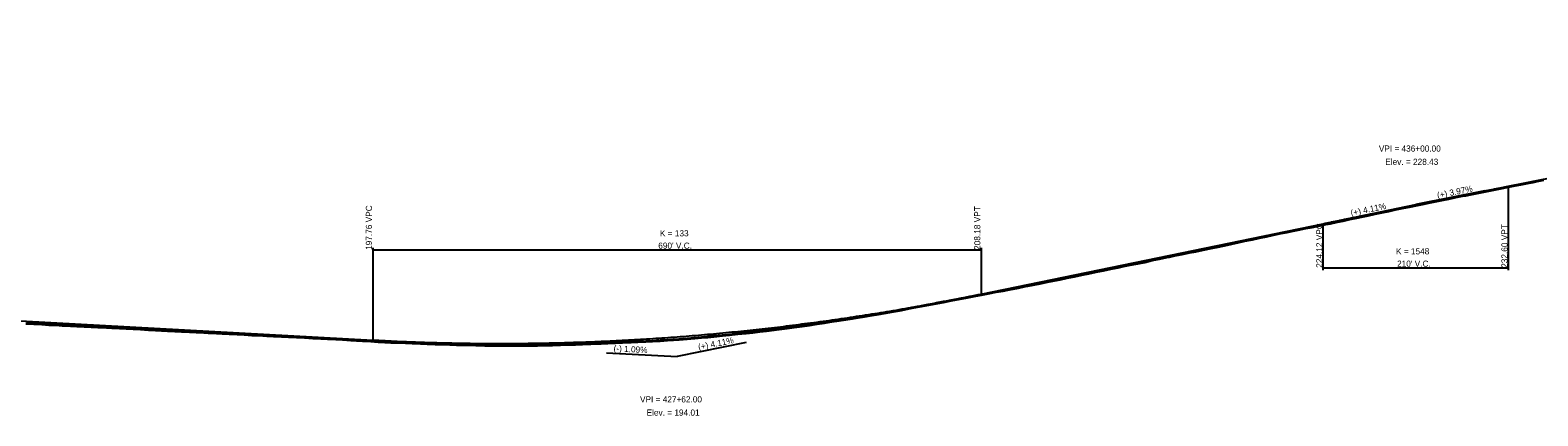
# Model space of a CAD drawing. Extents: x 1876258 to 1926563, y 729739 to 834437.
# Drawn here: x 1920391 to 1922101, y 830907 to 831344 of the extents above; entities that cross this region are included whole.
import ezdxf

# ---------------------------------------------------------------- set-up
doc = ezdxf.new("R2010")
doc.units = 0
for name, color, linetype in [('RD_EX_BldgApp', 7, 'Continuous'), ('RD_EX_H2O_BlueLn', 7, 'Continuous'), ('RD_EX_RailRoad', 7, 'Continuous'), ('RD_HC_Data', 7, 'Continuous'), ('RD_HC_Data_Tic', 7, 'Continuous'), ('RD_HC_TX_Sta50', 7, 'Continuous'), ('RD_PD_ALT5_CL', 7, 'Continuous')]:
    doc.layers.add(name, color=color, linetype=linetype)

msp = doc.modelspace()

# ---------------------------------------------------------------- linework, layer by layer
at = {"layer": 'RD_EX_BldgApp'}
for points in [[(1921856.5, 831122.9), (1921861, 831123.8), (1921866.3, 831124.9), (1921874.3, 831126.6), (1921880.6, 831127.9), (1921888.2, 831129.5), (1921896, 831131.1), (1921901.3, 831132.2), (1921909, 831133.8), (1921916.9, 831135.5), (1921924.6, 831137.1), (1921932.4, 831138.8), (1921940.1, 831140.4), (1921947.5, 831141.9), (1921955.8, 831143.6), (1921964.9, 831145.5), (1921972.4, 831147), (1921979.3, 831148.4), (1921984.8, 831149.6), (1921992.6, 831151.2), (1922000.3, 831152.8), (1922008.6, 831154.4), (1922016.1, 831155.9), (1922019.7, 831156.6), (1922025.1, 831157.6), (1922030.6, 831158.8), (1922038.2, 831160.3), (1922045.8, 831161.8), (1922053.4, 831163.2), (1922059, 831164.4), (1922068.1, 831166.1), (1922075.7, 831167.6), (1922082.3, 831168.9), (1922091.5, 831170.7), (1922096.2, 831171.7), (1922100.6, 831172.6), (1922108.1, 831174.1)], [(1921080.6, 830990.5), (1921089.8, 830991), (1921097.2, 830991.4), (1921106.1, 830991.9), (1921114.2, 830992.4), (1921121.1, 830992.9), (1921127.4, 830993.4), (1921136.6, 830994), (1921145.2, 830994.8), (1921152.8, 830995.5), (1921159.9, 830996.1), (1921167, 830996.9), (1921176.5, 830997.8), (1921184.5, 830998.6), (1921194.1, 830999.6), (1921203.5, 831000.6), (1921211.2, 831001.4), (1921219, 831002.4), (1921226.7, 831003.3), (1921235.1, 831004.2), (1921241, 831004.9), (1921250.1, 831006.1), (1921258.1, 831007.1), (1921267.1, 831008.4), (1921275.2, 831009.5), (1921284.1, 831011), (1921292.3, 831012.3), (1921300.7, 831013.6), (1921309, 831014.8), (1921313.9, 831015.6), (1921324.1, 831017.2), (1921325.9, 831017.5), (1921330.5, 831018.3), (1921337.7, 831019.5), (1921346.3, 831020.9), (1921353.7, 831022.2), (1921362.2, 831023.6), (1921370.6, 831025), (1921379.7, 831026.7), (1921388.1, 831028.3), (1921393.8, 831029.4), (1921402.5, 831031), (1921410.5, 831032.5), (1921419.1, 831034.1), (1921427.5, 831035.7), (1921436.2, 831037.4), (1921444.5, 831038.9), (1921452.7, 831040.5), (1921462.1, 831042.3), (1921470.4, 831043.9), (1921478.1, 831045.5), (1921487, 831047.2), (1921495.1, 831048.6), (1921502.1, 831050), (1921512.3, 831052), (1921520.5, 831053.6), (1921523, 831054.1), (1921528.9, 831055.3), (1921536.9, 831056.9), (1921545.2, 831058.5), (1921551.4, 831059.8), (1921559.5, 831061.4), (1921567.7, 831063.1), (1921575.9, 831064.8), (1921584.1, 831066.5), (1921592.2, 831068.1), (1921600.4, 831069.8), (1921608.7, 831071.5), (1921617.2, 831073.3), (1921625.3, 831074.9), (1921631.4, 831076.2), (1921639.2, 831077.8), (1921647.6, 831079.5), (1921655.6, 831081.1), (1921664, 831083), (1921672.2, 831084.7), (1921680.5, 831086.4), (1921683.6, 831087), (1921689.7, 831088.3), (1921698.1, 831090), (1921706.2, 831091.7), (1921713.6, 831093.1), (1921721.8, 831094.7), (1921730.9, 831096.7), (1921738.9, 831098.4), (1921745.9, 831099.8), (1921754.4, 831101.7), (1921761.3, 831103.2), (1921769.2, 831104.9), (1921777.7, 831106.7), (1921785.9, 831108.5), (1921793.6, 831110.1), (1921801.8, 831111.8), (1921810.4, 831113.6), (1921817.1, 831115), (1921823.9, 831116.4), (1921831.6, 831118), (1921838.3, 831119.3), (1921845.4, 831120.7), (1921850.8, 831121.8), (1921856.5, 831122.9)], [(1920386.4, 831011.4), (1920395.6, 831010.9), (1920404.8, 831010.5), (1920412.5, 831010.1), (1920420.5, 831009.8), (1920427.6, 831009.3), (1920437, 831008.8), (1920444.4, 831008.5), (1920452.6, 831008.1), (1920460.5, 831007.7), (1920468, 831007.3), (1920478.1, 831006.9), (1920483.9, 831006.6), (1920492.7, 831006.1), (1920500.1, 831005.7), (1920508.2, 831005.3), (1920516.7, 831004.9), (1920525.6, 831004.4), (1920533.5, 831004), (1920547.3, 831003.2), (1920555.3, 831002.9), (1920563.2, 831002.4), (1920572, 831002.1), (1920579.8, 831001.6), (1920588.4, 831001.1), (1920593.3, 831000.9), (1920602.6, 831000.5), (1920609.2, 831000.2), (1920617.1, 830999.8), (1920626, 830999.3), (1920634, 830998.8), (1920642.9, 830998.4), (1920650.6, 830998.1), (1920659.7, 830997.5), (1920667.5, 830997.1), (1920676.4, 830996.7), (1920684.3, 830996.3), (1920693.3, 830995.8), (1920702.5, 830995.4), (1920712, 830995), (1920721.2, 830994.6), (1920728.8, 830994.1), (1920738.1, 830993.6), (1920745.6, 830993.2), (1920755, 830992.5), (1920761.6, 830992.2), (1920768.4, 830991.9), (1920777.7, 830991.3), (1920786.2, 830990.8), (1920793.6, 830990.4), (1920800.5, 830990.1), (1920808, 830989.8), (1920817.1, 830989.4), (1920824.6, 830989.2), (1920834.3, 830988.8), (1920841.8, 830988.5), (1920850.9, 830988.1), (1920858.3, 830987.9), (1920867.5, 830987.6), (1920874.9, 830987.4), (1920881.2, 830987.2), (1920890.6, 830987.1), (1920896.9, 830986.9), (1920906.9, 830986.7), (1920915.6, 830986.6), (1920925, 830986.5), (1920932.4, 830986.4), (1920942, 830986.5), (1920949.1, 830986.5), (1920953.4, 830986.5), (1920959.2, 830986.5), (1920966.8, 830986.6), (1920976.1, 830986.8), (1920983.8, 830987), (1920992.9, 830987.2), (1921000.7, 830987.5), (1921009.8, 830987.7), (1921017.8, 830988), (1921027.3, 830988.3), (1921032.7, 830988.6), (1921039.2, 830988.9), (1921046.7, 830989.2), (1921055.4, 830989.5), (1921063.3, 830989.8), (1921073, 830990.2), (1921080.6, 830990.5)]]:
    msp.add_lwpolyline(points, dxfattribs=at)
at = {"layer": 'RD_EX_H2O_BlueLn'}
for p, q in [((1922068.1, 831072.4), (1922068.1, 831167.3)), ((1921858.1, 831072.4), (1921858.1, 831124.9)), ((1920780.1, 831097.7), (1920780.1, 830993.1)), ((1921470.1, 831097.7), (1921470.1, 831045.2)), ((1920780.1, 831095.2), (1921470.1, 831095.2)), ((1921858.1, 831074.9), (1922068.1, 831074.9))]:
    msp.add_line(p, q, dxfattribs=at)
at = {"layer": 'RD_HC_Data_Tic'}
msp.add_lwpolyline([(1920386.5, 831012.6), (1920395.7, 831012.1), (1920404.8, 831011.7), (1920412.6, 831011.4), (1920420.5, 831011), (1920427.6, 831010.6), (1920437.1, 831010.1), (1920444.4, 831009.7), (1920452.7, 831009.4), (1920460.5, 831009), (1920468.1, 831008.6), (1920478.1, 831008.1), (1920483.9, 831007.8), (1920492.8, 831007.4), (1920500.2, 831007), (1920508.3, 831006.5), (1920516.7, 831006.1), (1920525.6, 831005.6), (1920533.6, 831005.2), (1920547.4, 831004.5), (1920555.3, 831004.1), (1920563.3, 831003.7), (1920572, 831003.3), (1920579.9, 831002.9), (1920588.4, 831002.4), (1920593.4, 831002.2), (1920602.6, 831001.7), (1920609.3, 831001.4), (1920617.1, 831001), (1920626.1, 831000.5), (1920634, 831000.1), (1920642.9, 830999.7), (1920650.7, 830999.3), (1920659.7, 830998.7), (1920667.6, 830998.3), (1920676.5, 830998), (1920684.4, 830997.6), (1920693.4, 830997.1), (1920702.5, 830996.7), (1920712.1, 830996.3), (1920721.2, 830995.8), (1920728.8, 830995.3), (1920738.2, 830994.8), (1920745.7, 830994.4), (1920755.1, 830993.8), (1920761.7, 830993.5), (1920768.4, 830993.1), (1920777.8, 830992.6), (1920786.2, 830992.1), (1920793.7, 830991.7), (1920800.6, 830991.4), (1920808.1, 830991.1), (1920817.2, 830990.7), (1920824.6, 830990.4), (1920834.3, 830990), (1920841.8, 830989.8), (1920850.9, 830989.4), (1920858.3, 830989.1), (1920867.5, 830988.8), (1920874.9, 830988.7), (1920881.2, 830988.5), (1920890.6, 830988.3), (1920896.9, 830988.2), (1920906.9, 830988), (1920915.6, 830987.8), (1920925, 830987.7), (1920932.4, 830987.6), (1920942, 830987.7), (1920949.1, 830987.7), (1920953.4, 830987.8), (1920959.2, 830987.8), (1920966.7, 830987.9), (1920976, 830988.1), (1920983.7, 830988.3), (1920992.9, 830988.5), (1921000.7, 830988.7), (1921009.8, 830988.9), (1921017.8, 830989.2), (1921027.2, 830989.6), (1921032.6, 830989.8), (1921039.2, 830990.1), (1921046.7, 830990.4), (1921055.4, 830990.7), (1921063.3, 830991), (1921072.9, 830991.5), (1921080.6, 830991.8), (1921089.7, 830992.3), (1921097.1, 830992.7), (1921106, 830993.2), (1921114.1, 830993.7), (1921121, 830994.2), (1921127.3, 830994.6), (1921136.5, 830995.3), (1921145, 830996), (1921152.7, 830996.8), (1921159.8, 830997.4), (1921166.9, 830998.1), (1921176.4, 830999), (1921184.4, 830999.8), (1921193.9, 831000.9), (1921203.4, 831001.9), (1921211, 831002.6), (1921218.8, 831003.6), (1921226.6, 831004.5), (1921234.9, 831005.5), (1921240.8, 831006.2), (1921249.9, 831007.4), (1921258, 831008.3), (1921266.9, 831009.6), (1921275, 831010.8), (1921283.9, 831012.2), (1921292.1, 831013.5), (1921300.6, 831014.8), (1921308.8, 831016), (1921313.7, 831016.8), (1921323.9, 831018.4), (1921325.7, 831018.7), (1921330.3, 831019.6), (1921335.1, 831020.3), (1921337.5, 831020.7), (1921344.5, 831021.9), (1921346, 831022.1), (1921353.5, 831023.4), (1921353.9, 831023.5), (1921362, 831024.8), (1921363.3, 831025.1), (1921370.4, 831026.3), (1921372.6, 831026.7), (1921379.4, 831028), (1921382, 831028.4), (1921387.9, 831029.6), (1921391.4, 831030.2), (1921393.6, 831030.6), (1921400.8, 831032), (1921402.3, 831032.3), (1921410.1, 831033.7), (1921410.3, 831033.7), (1921418.9, 831035.4), (1921419.5, 831035.5), (1921427.3, 831037), (1921428.9, 831037.3), (1921435.9, 831038.6), (1921438.3, 831039), (1921444.3, 831040.2), (1921447.7, 831040.8), (1921452.4, 831041.7), (1921457, 831042.6), (1921461.9, 831043.6), (1921466.4, 831044.4), (1921470.2, 831045.2), (1921475.8, 831046.3), (1921477.9, 831046.7), (1921485.2, 831048.1), (1921486.8, 831048.4), (1921494.6, 831049.8), (1921494.9, 831049.9), (1921501.8, 831051.2), (1921504, 831051.6), (1921512.1, 831053.2), (1921513.3, 831053.5), (1921520.3, 831054.8), (1921522.7, 831055.3), (1921528.7, 831056.5), (1921536.7, 831058.1), (1921544.9, 831059.8), (1921551.1, 831061), (1921559.3, 831062.6), (1921567.4, 831064.3), (1921575.7, 831066), (1921583.8, 831067.7), (1921592, 831069.4), (1921600.2, 831071), (1921608.4, 831072.7), (1921616.9, 831074.5), (1921625, 831076.2), (1921631.1, 831077.4), (1921639, 831079), (1921647.3, 831080.7), (1921655.3, 831082.4), (1921663.7, 831084.2), (1921672, 831085.9), (1921680.2, 831087.6), (1921683.4, 831088.2), (1921689.4, 831089.5), (1921697.8, 831091.2), (1921706, 831092.9), (1921713.4, 831094.3), (1921721.6, 831096), (1921730.6, 831098), (1921738.7, 831099.6), (1921745.6, 831101.1), (1921754.1, 831102.9), (1921761, 831104.4), (1921768.9, 831106.1), (1921777.4, 831108), (1921785.7, 831109.7), (1921793.3, 831111.4), (1921801.5, 831113.1), (1921810.1, 831114.8), (1921816.9, 831116.2), (1921823.7, 831117.7), (1921831.3, 831119.2), (1921838.1, 831120.5), (1921845.1, 831122), (1921850.6, 831123), (1921856.3, 831124.1), (1921860.7, 831125.1), (1921866, 831126.2), (1921874, 831127.8), (1921880.3, 831129.1), (1921888, 831130.7), (1921895.7, 831132.3), (1921901.1, 831133.4), (1921908.8, 831135), (1921916.6, 831136.7), (1921924.3, 831138.4), (1921932.1, 831140), (1921939.8, 831141.6), (1921947.3, 831143.1), (1921955.6, 831144.8), (1921964.7, 831146.7), (1921972.1, 831148.2), (1921979, 831149.6), (1921984.6, 831150.8), (1921992.3, 831152.5), (1922000.1, 831154.1), (1922008.4, 831155.7), (1922015.8, 831157.1), (1922019.4, 831157.8), (1922024.8, 831158.9), (1922030.4, 831160), (1922038, 831161.6), (1922045.6, 831163), (1922053.1, 831164.5), (1922058.8, 831165.6), (1922067.8, 831167.3), (1922075.5, 831168.8), (1922082.1, 831170.2), (1922091.3, 831172), (1922096, 831172.9), (1922100.3, 831173.8), (1922107.9, 831175.3)], dxfattribs=at)
at = {"layer": 'RD_HC_TX_Sta50'}
for p, q in [((1922041.5, 831162), (1921963.1, 831146.5)), ((1921884.7, 831130.4), (1921963.1, 831146.5)), ((1921045.2, 830978.7), (1921125.1, 830974.4)), ((1921203.4, 830990.4), (1921125.1, 830974.4))]:
    msp.add_line(p, q, dxfattribs=at)
at = {"layer": 'RD_PD_ALT5_CL'}
for p, q in [((1922068.1, 831167.3), (1922958.1, 831344.1)), ((1921470.1, 831045.2), (1921858.1, 831124.9)), ((1920330.2, 831017.5), (1920780.1, 830993.1))]:
    msp.add_line(p, q, dxfattribs=at)
for points in [[(1921858.1, 831124.9), (1921862.3, 831125.8), (1921866.5, 831126.6), (1921870.7, 831127.5), (1921874.9, 831128.3), (1921879.1, 831129.2), (1921883.3, 831130.1), (1921887.5, 831130.9), (1921891.7, 831131.8), (1921895.9, 831132.6), (1921900.1, 831133.5), (1921904.3, 831134.4), (1921908.5, 831135.2), (1921912.7, 831136.1), (1921916.9, 831136.9), (1921921.1, 831137.8), (1921925.3, 831138.6), (1921929.5, 831139.5), (1921933.7, 831140.3), (1921937.9, 831141.2), (1921942.1, 831142), (1921946.3, 831142.9), (1921950.5, 831143.7), (1921954.7, 831144.6), (1921958.9, 831145.4), (1921963.1, 831146.3), (1921967.3, 831147.1), (1921971.5, 831148), (1921975.7, 831148.8), (1921979.9, 831149.7), (1921984.1, 831150.5), (1921988.3, 831151.4), (1921992.5, 831152.2), (1921996.7, 831153.1), (1922000.9, 831153.9), (1922005.1, 831154.7), (1922009.3, 831155.6), (1922013.5, 831156.4), (1922017.7, 831157.3), (1922021.9, 831158.1), (1922026.1, 831158.9), (1922030.3, 831159.8), (1922034.5, 831160.6), (1922038.7, 831161.5), (1922042.9, 831162.3), (1922047.1, 831163.1), (1922051.3, 831164), (1922055.5, 831164.8), (1922059.7, 831165.6), (1922063.9, 831166.5), (1922068.1, 831167.3)], [(1920780.1, 830993.1), (1920793.9, 830992.4), (1920807.7, 830991.7), (1920821.5, 830991.2), (1920835.3, 830990.7), (1920849.1, 830990.2), (1920862.9, 830989.9), (1920876.7, 830989.6), (1920890.5, 830989.4), (1920904.3, 830989.2), (1920918.1, 830989.2), (1920931.9, 830989.2), (1920945.7, 830989.3), (1920959.5, 830989.4), (1920973.3, 830989.6), (1920987.1, 830989.9), (1921000.9, 830990.3), (1921014.7, 830990.7), (1921028.5, 830991.2), (1921042.3, 830991.8), (1921056.1, 830992.4), (1921069.9, 830993.2), (1921083.7, 830993.9), (1921097.5, 830994.8), (1921111.3, 830995.7), (1921125.1, 830996.7), (1921138.9, 830997.8), (1921152.7, 830999), (1921166.5, 831000.2), (1921180.3, 831001.5), (1921194.1, 831002.9), (1921207.9, 831004.3), (1921221.7, 831005.8), (1921235.5, 831007.4), (1921249.3, 831009), (1921263.1, 831010.8), (1921276.9, 831012.6), (1921290.7, 831014.4), (1921304.5, 831016.4), (1921318.3, 831018.4), (1921332.1, 831020.5), (1921345.9, 831022.6), (1921359.7, 831024.8), (1921373.5, 831027.1), (1921387.3, 831029.5), (1921401.1, 831031.9), (1921414.9, 831034.4), (1921428.7, 831037), (1921442.5, 831039.7), (1921456.3, 831042.4), (1921470.1, 831045.2)]]:
    msp.add_spline(points, degree=3, dxfattribs=at)

# ---------------------------------------------------------------- texts
at = {"layer": 'RD_EX_H2O_BlueLn'}
for s, p in [('K = 133', (1921105.7, 831110.5)), ("690' V.C.", (1921103.8, 831096.5)), ('K = 1548', (1921940.6, 831090.1)), ("210' V.C.", (1921941.8, 831076.1))]:
    msp.add_text(s, height=7, dxfattribs=at).set_placement(p)
at = {"layer": 'RD_EX_RailRoad'}
for s, p in [('197.76 VPC', (1920779.1, 831095.2)), ('208.18 VPT', (1921469.1, 831095.2)), ('224.12 VPC', (1921857.1, 831074.9)), ('232.60 VPT', (1922067.1, 831074.9))]:
    msp.add_text(s, height=7, rotation=90, dxfattribs=at).set_placement(p)
at = {"layer": 'RD_HC_Data'}
for s, p in [('VPI = 436+00.00', (1921921.1, 831206.5)), ('Elev. = 228.43', (1921928.4, 831191.5)), ('VPI = 427+62.00', (1921083.1, 830922.4)), ('Elev. = 194.01', (1921090.6, 830907.4))]:
    msp.add_text(s, height=7, dxfattribs=at).set_placement(p)
at = {"layer": 'RD_HC_TX_Sta50'}
for s, rotation, p in [('(+) 3.97%', 11.2327, (1921987.9, 831153.4)), ('(+) 4.11%', 11.6061, (1921889.9, 831133.5)), ('(+) 4.11%', 11.6061, (1921149.8, 830981.5)), ('(-) 1.09%', 356.8933, (1921053, 830980.3))]:
    msp.add_text(s, height=7, rotation=rotation, dxfattribs=at).set_placement(p)

doc.saveas('drawing.dxf')
